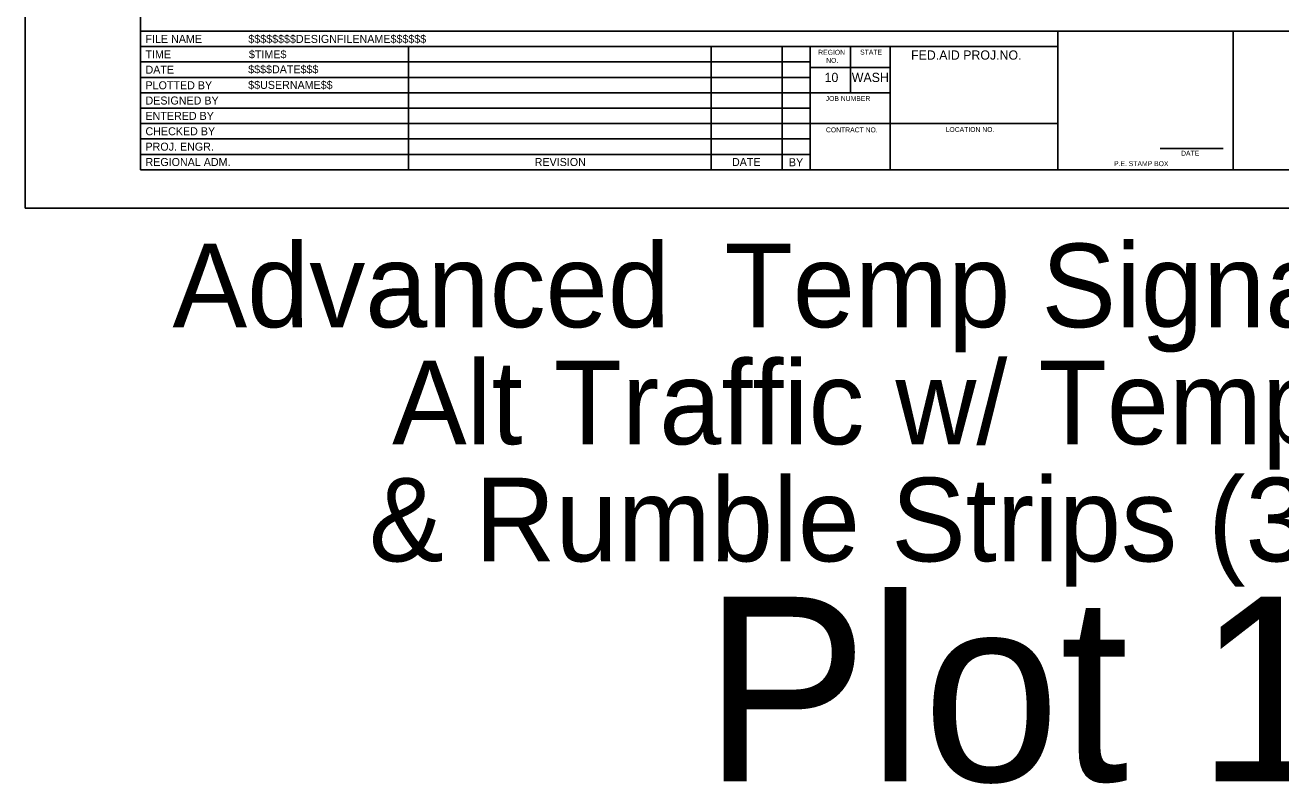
# Model space of a CAD drawing. Extents: x 99976 to 100136, y 99905 to 100011.
# Drawn here: x 99999.06 to 100009.27, y 99965.01 to 99971.18 of the extents above; entities that cross this region are included whole.
import ezdxf

# ---------------------------------------------------------------- set-up
doc = ezdxf.new("R2010")
doc.units = 0
for name, color, linetype in [('SH_GI_PlotLimits', 7, 'Continuous'), ('SH_GI_SheetBorder', 7, 'Continuous'), ('SH_GI_SheetLocationText', 7, 'Continuous'), ('SH_GI_SheetTextInCells', 7, 'Continuous'), ('SH_GI_TitleBlockText', 7, 'Continuous')]:
    doc.layers.add(name, color=color, linetype=linetype)

msp = doc.modelspace()

# ---------------------------------------------------------------- linework, layer by layer
at = {"layer": 'SH_GI_PlotLimits'}
msp.add_lwpolyline([(99999.062, 99969.687), (100016.062, 99969.687), (100016.062, 99980.687), (99999.062, 99980.687)], close=True, dxfattribs=at)
at = {"layer": 'SH_GI_SheetBorder'}
for p, q in [((100000, 99980.375), (100000, 99970)), ((100000, 99971.126), (100015.75, 99971.126)), ((100007.457, 99970), (100007.457, 99971.126)), ((100008.883, 99970), (100008.883, 99971.126)), ((100000, 99971.001), (100007.457, 99971.001)), ((100002.179, 99971.001), (100002.179, 99970)), ((100004.641, 99971.001), (100004.641, 99970)), ((100005.216, 99971.001), (100005.216, 99970)), ((100005.445, 99971.001), (100005.445, 99970)), ((100005.772, 99970.625), (100005.772, 99971.001)), ((100006.096, 99970), (100006.096, 99971.001)), ((100000, 99970.876), (100002.182, 99970.876)), ((100002.182, 99970.876), (100005.447, 99970.876)), ((100006.096, 99970.831), (100005.447, 99970.831)), ((100000, 99970.751), (100002.182, 99970.751)), ((100002.182, 99970.751), (100005.447, 99970.751)), ((100000, 99970.625), (100005.447, 99970.625)), ((100006.096, 99970.625), (100005.447, 99970.625)), ((100000, 99970.5), (100005.447, 99970.5)), ((100000, 99970.375), (100005.447, 99970.375)), ((100007.457, 99970.375), (100005.447, 99970.375)), ((100000, 99970.25), (100005.447, 99970.25)), ((100008.29, 99970.173), (100008.802, 99970.173)), ((100000, 99970.125), (100005.447, 99970.125)), ((100000, 99970), (100015.75, 99970))]:
    msp.add_line(p, q, dxfattribs=at)

# ---------------------------------------------------------------- texts
at = {"layer": 'SH_GI_SheetLocationText'}
for s, height, p in [('Advanced', 0.68, (100000.261, 99968.719)), (' Temp Signal-Controlled', 0.68, (100004.495, 99968.719)), ('Alt Traffic w/ Temp Barrier', 0.68, (100002.046, 99967.767)), ('& Rumble Strips (30 mph)', 0.68, (100001.858, 99966.815)), ('Plot 11', 1.5, (100004.576, 99965.027))]:
    msp.add_text(s, height=height, dxfattribs=at).set_placement(p)
at = {"layer": 'SH_GI_SheetTextInCells'}
for s, height, p in [('FILE NAME', 0.0651, (100000.041, 99971.031)), ('REGION', 0.04, (100005.51, 99970.935)), ('STATE', 0.04, (100005.851, 99970.936)), ('TIME', 0.0651, (100000.041, 99970.906)), ('NO.', 0.04, (100005.575, 99970.869)), ('FED.AID PROJ.NO.', 0.07506, (100006.265, 99970.895)), ('DATE', 0.0651, (100000.041, 99970.781)), ('10', 0.0751, (100005.562, 99970.713)), ('WASH', 0.0751, (100005.783, 99970.713)), ('PLOTTED BY', 0.0651, (100000.041, 99970.654)), ('DESIGNED BY', 0.06505, (100000.041, 99970.53)), ('JOB NUMBER', 0.04, (100005.571, 99970.559)), ('ENTERED BY', 0.0651, (100000.041, 99970.405)), ('CHECKED BY', 0.0651, (100000.041, 99970.28)), ('CONTRACT NO.', 0.04003, (100005.573, 99970.304)), ('LOCATION NO.', 0.04003, (100006.546, 99970.307)), ('PROJ. ENGR.', 0.06505, (100000.041, 99970.155)), ('REGIONAL ADM.', 0.06505, (100000.041, 99970.03)), ('REVISION', 0.0651, (100003.205, 99970.03)), ('DATE', 0.0651, (100004.809, 99970.03)), ('BY', 0.0651, (100005.272, 99970.028)), ('P.E. STAMP BOX', 0.04003, (100007.915, 99970.029)), ('DATE', 0.04, (100008.46, 99970.114))]:
    msp.add_text(s, height=height, dxfattribs=at).set_placement(p)
at = {"layer": 'SH_GI_TitleBlockText'}
for s, height, p in [('$$$$$$$$DESIGNFILENAME$$$$$$', 0.06505, (100000.877, 99971.031)), ('$TIME$', 0.0651, (100000.882, 99970.906)), ('$$$$DATE$$$', 0.06505, (100000.876, 99970.784)), ('$$USERNAME$$', 0.06505, (100000.876, 99970.657))]:
    msp.add_text(s, height=height, dxfattribs=at).set_placement(p)

doc.saveas('drawing.dxf')
